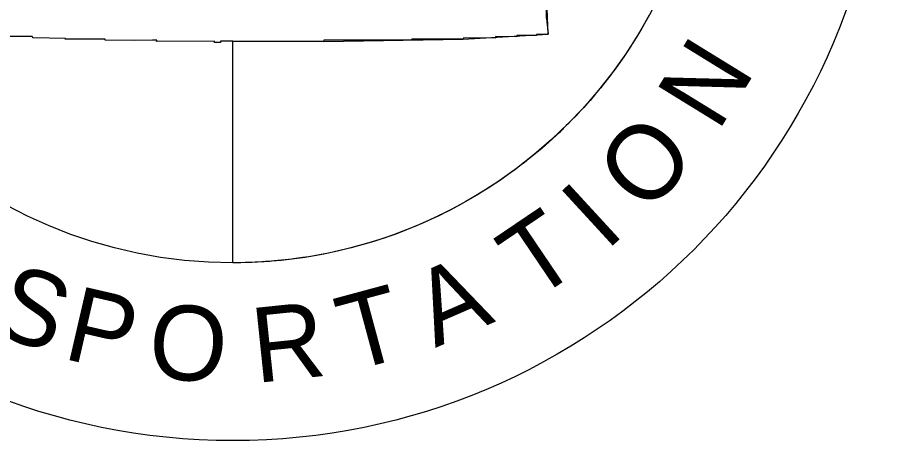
# Model space of a CAD drawing. Extents: x 0 to 1.42, y 0 to 0.92.
# Drawn here: x 1.34592 to 1.37918, y 0.07917 to 0.0954 of the extents above; entities that cross this region are included whole.
import ezdxf

# ---------------------------------------------------------------- set-up
doc = ezdxf.new("R2010")
doc.units = 0
doc.layers.add('P_ODOT_PLAN_TBlock', color=7, linetype='Continuous')

msp = doc.modelspace()

# ---------------------------------------------------------------- linework, layer by layer
at = {"layer": 'P_ODOT_PLAN_TBlock'}
for points in [[(1.3701531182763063, 0.0954814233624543), (1.37006764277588, 0.09532600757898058), (1.370039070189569, 0.09527485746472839), (1.3698975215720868, 0.09502704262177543), (1.3698436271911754, 0.09493498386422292), (1.3697841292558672, 0.09483480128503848), (1.3697048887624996, 0.09470358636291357), (1.369632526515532, 0.09458596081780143), (1.3695513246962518, 0.09445618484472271), (1.3695163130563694, 0.09440099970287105), (1.3694977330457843, 0.09437188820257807), (1.3694862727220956, 0.09435399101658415), (1.3693850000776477, 0.09419781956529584), (1.369148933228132, 0.0938468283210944), (1.3691190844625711, 0.09380365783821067), (1.369049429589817, 0.09370258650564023), (1.3688462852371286, 0.09341974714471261), (1.3687863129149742, 0.09333977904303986), (1.3687714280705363, 0.09331976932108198), (1.3686407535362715, 0.09314373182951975), (1.3683544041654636, 0.09277821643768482), (1.3682926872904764, 0.09270391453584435), (1.3682235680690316, 0.09261936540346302), (1.368136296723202, 0.09251406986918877), (1.3680592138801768, 0.092422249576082), (1.3678830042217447, 0.09221730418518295), (1.36783409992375, 0.09216152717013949), (1.367739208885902, 0.09205442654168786), (1.3677077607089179, 0.09201879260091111), (1.367556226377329, 0.09185221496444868), (1.3674855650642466, 0.09177637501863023), (1.3674633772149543, 0.09175260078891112), (1.367346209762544, 0.0916281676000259), (1.3671768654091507, 0.0914530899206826), (1.3670468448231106, 0.09132149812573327), (1.3669734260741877, 0.09124839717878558), (1.3668589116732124, 0.09113601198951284), (1.3668107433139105, 0.09108931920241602), (1.3668026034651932, 0.09108160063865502), (1.3667904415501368, 0.09106974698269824), (1.366707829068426, 0.09099072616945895), (1.3665930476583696, 0.09088289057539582), (1.3664480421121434, 0.0907485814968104), (1.3663203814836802, 0.09063317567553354), (1.366041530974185, 0.09038862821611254), (1.3656488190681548, 0.0900595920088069), (1.3654611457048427, 0.0899090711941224), (1.3653534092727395, 0.0898245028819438), (1.3652450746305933, 0.08974062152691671), (1.365001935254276, 0.08955757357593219), (1.364836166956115, 0.08943614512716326), (1.3644078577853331, 0.08913587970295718), (1.364134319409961, 0.08895333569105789), (1.3640398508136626, 0.08889194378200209), (1.3639804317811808, 0.08885375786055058), (1.3638489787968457, 0.08877044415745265), (1.3637908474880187, 0.08873392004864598), (1.3633680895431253, 0.08847883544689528), (1.3631193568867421, 0.08833584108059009), (1.3630261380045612, 0.0882835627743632), (1.3630075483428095, 0.088273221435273), (1.3627763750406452, 0.08814672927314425), (1.3625406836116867, 0.08802285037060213), (1.3624402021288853, 0.08797122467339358), (1.3622195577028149, 0.08786063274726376), (1.3621544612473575, 0.08782869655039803), (1.36208479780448, 0.08779488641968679), (1.3620604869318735, 0.08778317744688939), (1.3620502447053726, 0.08777826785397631), (1.3620467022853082, 0.0877765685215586), (1.3619251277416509, 0.08771922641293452), (1.3615238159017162, 0.08753584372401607), (1.3613468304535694, 0.08745881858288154), (1.3612122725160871, 0.08740176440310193), (1.3610406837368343, 0.08733075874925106), (1.3607063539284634, 0.0871985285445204), (1.3604689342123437, 0.0871091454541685), (1.360349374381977, 0.0870655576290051), (1.3602293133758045, 0.08702291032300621), (1.3600233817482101, 0.08695151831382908), (1.3598165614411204, 0.08688280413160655), (1.3593971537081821, 0.08675159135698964), (1.3586618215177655, 0.08654825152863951), (1.358194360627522, 0.08643590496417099), (1.3580163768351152, 0.08639659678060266), (1.3576691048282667, 0.08632462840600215), (1.3573168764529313, 0.08626001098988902), (1.357092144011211, 0.08622212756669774), (1.3568664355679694, 0.08618698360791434), (1.3565127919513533, 0.08613776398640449), (1.3564640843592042, 0.08613156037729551), (1.35605603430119, 0.0860846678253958), (1.3557709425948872, 0.08605735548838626), (1.3556061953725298, 0.08604365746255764), (1.3555914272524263, 0.08604258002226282), (1.355551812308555, 0.08603947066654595), (1.3554418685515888, 0.0860315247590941), (1.3553808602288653, 0.08602737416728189), (1.3553575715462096, 0.08602587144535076), (1.3551232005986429, 0.08601235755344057), (1.355040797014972, 0.08600812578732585), (1.3549082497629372, 0.08600238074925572), (1.3546532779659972, 0.08599370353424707), (1.3544945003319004, 0.08599044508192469), (1.3542895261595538, 0.08598809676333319), (1.3542164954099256, 0.08598792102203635), (1.3541833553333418, 0.08598788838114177), (1.3541833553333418, 0.09448400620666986), (1.3576586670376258, 0.09447772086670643), (1.3630197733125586, 0.09456753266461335), (1.3662813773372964, 0.09475265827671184), (1.3659748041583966, 0.102508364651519)], [(1.366204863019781, 0.0963915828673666), (1.3661973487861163, 0.0953954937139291), (1.3662114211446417, 0.09536166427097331), (1.3662813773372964, 0.09475265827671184), (1.365834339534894, 0.09474853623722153), (1.3658260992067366, 0.09470937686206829), (1.36507828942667, 0.0946990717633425), (1.3650659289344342, 0.09465785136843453), (1.364260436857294, 0.09466197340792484), (1.364250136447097, 0.09460838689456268), (1.3630281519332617, 0.09461573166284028), (1.3630197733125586, 0.09456753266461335), (1.3610487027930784, 0.09456543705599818), (1.3610424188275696, 0.0945214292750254), (1.3576680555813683, 0.09452703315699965), (1.3576586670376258, 0.09447772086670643), (1.3541862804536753, 0.09448400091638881), (1.3537051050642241, 0.09448328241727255), (1.3537086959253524, 0.0944329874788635), (1.3534752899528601, 0.09443514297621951), (1.3534810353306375, 0.09448328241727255), (1.3512593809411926, 0.09448145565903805), (1.3512646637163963, 0.0945267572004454), (1.351102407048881, 0.0945260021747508), (1.3504260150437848, 0.09451830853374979), (1.3492844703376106, 0.09452421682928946), (1.3492884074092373, 0.09456951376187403), (1.3477591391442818, 0.09456360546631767), (1.3477658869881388, 0.09459511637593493), (1.3465247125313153, 0.09461420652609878), (1.346482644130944, 0.09466439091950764), (1.3454023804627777, 0.09466153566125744)]]:
    msp.add_lwpolyline(points, dxfattribs=at)
for radius in [0.025000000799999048, 0.01817878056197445]:
    msp.add_circle((1.3541833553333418, 0.10416666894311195), radius, dxfattribs=at)

# ---------------------------------------------------------------- texts
for s, height, rotation, p in [('N', 0.0028694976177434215, 58.37169331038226, (1.3727884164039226, 0.09097416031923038)), ('O', 0.0028694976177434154, 47.81128724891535, (1.3700554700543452, 0.08778782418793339)), ('I', 0.002869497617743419, 42.57913222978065, (1.3684957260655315, 0.08640866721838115)), ('T', 0.0028694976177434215, 34.07346227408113, (1.3657117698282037, 0.08448707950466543)), ('A', 0.0028694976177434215, 23.606808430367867, (1.3619448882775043, 0.08272024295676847)), ('S', 0.0028694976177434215, 339.5081090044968, (1.3448327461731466, 0.0833638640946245)), ('T', 0.0028694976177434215, 15.101138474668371, (1.3586874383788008, 0.08180813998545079)), ('P', 0.0028694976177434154, 346.9746918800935, (1.3476153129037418, 0.08232516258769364)), ('O', 0.0028694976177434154, 355.3787969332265, (1.3508780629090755, 0.08159975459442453)), ('R', 0.0028694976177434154, 5.939202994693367, (1.3550699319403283, 0.08137621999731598))]:
    msp.add_text(s, height=height, rotation=rotation, dxfattribs=at).set_placement(p)

doc.saveas('drawing.dxf')
